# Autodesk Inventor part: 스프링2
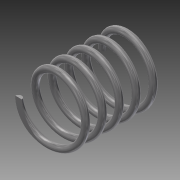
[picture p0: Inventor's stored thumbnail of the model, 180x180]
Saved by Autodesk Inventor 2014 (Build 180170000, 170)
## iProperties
Created: 2016-10
Part Number: 스프링2
Material: 강철, 탄소
Document SubType Name: Modeling
Designer: 703-16
Density: 7.87 g/cm^3
Appearance: 반연마
Mass: 6.87656 g
Surface Area: 17.7397 cm^2
Volume: 0.873769 cm^3
Author: 703-16
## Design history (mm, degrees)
sketch "스케치1"
  geometry: L1 (0, 0)-(-9, 0); L2 (-9, 0)-(-9, 26); L3 (-9, 26)-(0, 26); L4 (0, 26)-(0, 0); C1 r 1 at (-9, 0)
  constraints: 8 end point, 2 parallel, 1 centre point, 1 coincident, 1 horizontal, 1 perpendicular
  dimensions: "d0" = 26 distance of L3.end L1.start (derived); "d1" = 18 diameter of L2 L4; "d2" = 2 diameter of C1
feature "코일1" sketch "스케치1" pitch "d3" = 10; turns "d5" = 5; dims "d4" = 26 (= d0), "d6" = 0, angle "d7" = 90 deg, angle "d8" = 90 deg, "d9" = 0, "d10" = 0
node "작업 평면1"
sketch "스케치2"
  geometry: L1 (0, 0)-(-2, 0) reference; 1 further point
  constraints: 1 horizontal alignment
extrude "돌출1" cut sketch "스케치2" distance "d11" = 10; taper "d12" = 0 deg
sketch "스케치3"
  geometry: L1 (8, 0)-(10, 0) reference; 1 further point
  constraints: 1 horizontal alignment
extrude "돌출2" cut sketch "스케치3" distance "d13" = 10; taper "d14" = 0 deg
node "솔리드1"
node "절단 모서리 투영1"
node "절단 모서리 투영2"
